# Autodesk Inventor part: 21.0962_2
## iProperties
Company: MiniTec Framing Systems, LLC
Created: 2011-07
Part Number: 21.0962_2
Material: Aluminum-6061
Description: L = 1.89", MILL TO 21.0962/2
Document SubType Name: Modeling
Designer: Administrator
Stock Number: 20.1000 PROFILE 19X32
Density: 2.71 g/cm^3
Mass: 49.1676 g
Surface Area: 87.3127 cm^2
Volume: 18.143 cm^3
Vendor: F
FINISH: CLEAR ANODIZED
Author: Administrator
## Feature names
1. Extrusion1
2. Extrusion2
